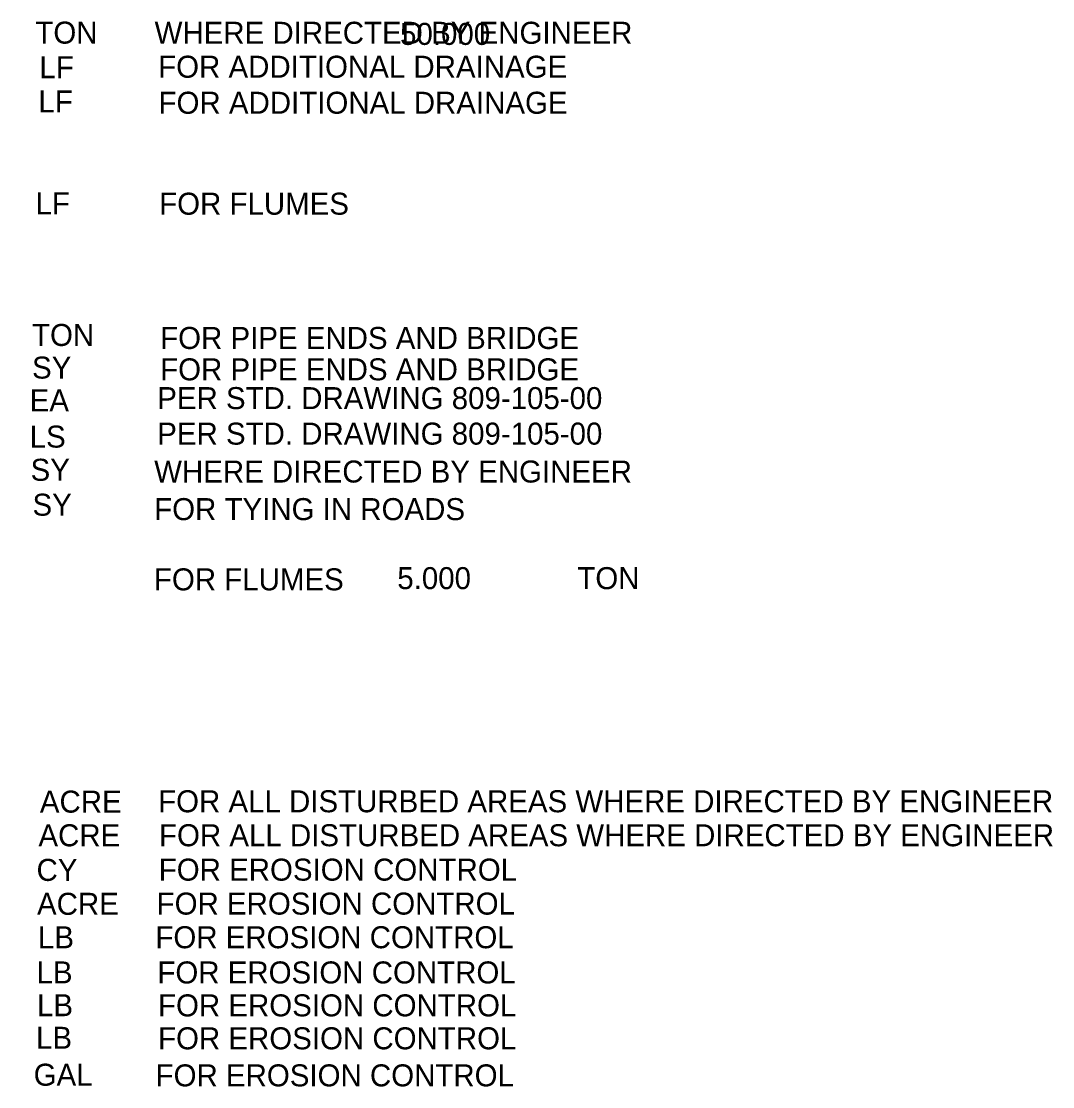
# Model space of a CAD drawing. Extents: x -13615 to 47191, y -1934 to 4415.
# Drawn here: x -11338.5 to -10963.1, y 1111 to 1499 of the extents above; entities that cross this region are included whole.
import ezdxf

# ---------------------------------------------------------------- set-up
doc = ezdxf.new("R2010")
doc.units = 0
doc.layers.add('Default', color=7, linetype='Continuous')

msp = doc.modelspace()

# ---------------------------------------------------------------- texts
at = {"layer": 'Default'}
for s, height, p in [('MAINTENANCE STONE                                                                                                                                            50.000     ', 8.01562, (-11735.47, 1490.39)), ('TON', 8.016, (-11333.38, 1490.85)), ('WHERE DIRECTED BY ENGINEER', 8.0156, (-11289.97, 1490.8)), ('LF', 8.016, (-11331.92, 1478.26)), ('FOR ADDITIONAL DRAINAGE', 8.0156, (-11288.68, 1478.44)), ('LF', 8.016, (-11332.28, 1465.78)), ('FOR ADDITIONAL DRAINAGE', 8.0156, (-11288.54, 1465.32)), ('LF', 8.016, (-11333.35, 1428.69)), ('FOR FLUMES', 8.016, (-11288.32, 1428.56)), ('TON', 8.016, (-11334.59, 1380.76)), ('FOR PIPE ENDS AND BRIDGE', 8.0156, (-11287.96, 1379.67)), ('SY', 8.016, (-11334.58, 1368.88)), ('FOR PIPE ENDS AND BRIDGE', 8.0156, (-11287.96, 1368.24)), ('PER STD. DRAWING 809-105-00', 8.0156, (-11289.02, 1357.76)), ('EA', 8.016, (-11335.44, 1356.95)), ('LS', 8.016, (-11335.44, 1343.75)), ('PER STD. DRAWING 809-105-00', 8.0156, (-11289.02, 1344.83)), ('SY', 8.016, (-11335.12, 1331.66)), ('WHERE DIRECTED BY ENGINEER', 8.0156, (-11290.13, 1331.03)), ('SY', 8.016, (-11334.42, 1318.95)), ('FOR TYING IN ROADS', 8.0156, (-11290.13, 1317.34)), ('HOT MIX  ASPH. CONC. SURF. CR. FOR DITCH PAVING                                                                                     5.000             TON', 8.01562, (-11736.45, 1292.21)), ('FOR FLUMES', 8.016, (-11290.22, 1291.77)), ('ACRE', 8.016, (-11331.74, 1210.83)), ('FOR ALL DISTURBED AREAS WHERE DIRECTED BY ENGINEER', 8.0156, (-11288.7, 1210.96)), ('ACRE', 8.016, (-11332.26, 1198.57)), ('FOR ALL DISTURBED AREAS WHERE DIRECTED BY ENGINEER', 8.0156, (-11288.37, 1198.59)), ('CY', 8.016, (-11332.95, 1185.97)), ('FOR EROSION CONTROL', 8.0156, (-11288.47, 1186.06)), ('ACRE', 8.016, (-11332.78, 1173.62)), ('FOR EROSION CONTROL', 8.0156, (-11289.24, 1173.7)), ('LB', 8.016, (-11332.43, 1161.44)), ('FOR EROSION CONTROL', 8.0156, (-11289.69, 1161.45)), ('LB', 8.016, (-11332.95, 1148.66)), ('FOR EROSION CONTROL', 8.0156, (-11288.96, 1148.63)), ('LB', 8.016, (-11332.78, 1136.7)), ('FOR EROSION CONTROL', 8.0156, (-11288.73, 1136.64)), ('LB', 8.016, (-11333.13, 1124.84)), ('FOR EROSION CONTROL', 8.0156, (-11288.72, 1124.64)), ('GAL', 8.016, (-11333.99, 1111.39)), ('FOR EROSION CONTROL', 8.0156, (-11289.61, 1111.15))]:
    msp.add_text(s, height=height, dxfattribs=at).set_placement(p)

doc.saveas('drawing.dxf')
